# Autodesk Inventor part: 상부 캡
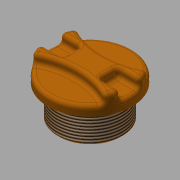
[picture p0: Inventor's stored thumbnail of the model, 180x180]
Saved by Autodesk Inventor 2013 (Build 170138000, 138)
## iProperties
Created: 2016-09
Part Number: 상부 캡
Material: PC/ABS 플라스틱
Document SubType Name: Modeling
Designer: mduedu
Density: 1.493 g/cm^3
Author: mduedu
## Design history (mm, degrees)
sketch "스케치1"
  geometry: C1 r 22.5 at (0, 0); 1 further point
  constraints: 1 centre point, 1 coincident
  dimensions: "d0" = 45 diameter of C1
extrude "돌출1" new body sketch "스케치1" distance "d1" = 10; taper "d2" = 0 deg
sketch "스케치2" dims "d4" = 80
  geometry: C1 r 22.5 at (0, 0) reference; 3 further points
  constraints: 3 vertical alignment, 2 other
  dimensions: "d3" = 7 distance of point (0, 7) point (0, 0)
extrude "돌출2" cut sketch "스케치2" distance "d5" = 5; taper "d6" = 0 deg
sketch "스케치3"
  geometry: L1 (-22.5, 0)-(0, 0); L2 (-21.937, 5)-(-10, 5); L3 (-10, 5)-(-10, -5); L4 (-10, -5)-(-21.937, -5); A1 r 22.5 centre (0, 0) between (-19.118, 11.864) and (-19.118, -11.864) reference; A2 r 22.5 centre (0, 0) between (-21.937, 5) and (-21.937, -5); 1 further point
  constraints: 8 end point, 5 point on circle, 2 horizontal, 1 centre point, 1 coincident, 1 parallel, 1 perpendicular, 1 symmetric about line
  dimensions: "d7" = 10 distance from line of L3 point (0, 0); "d8" = 10 distance of L2.end L3.end
extrude "돌출3" cut sketch "스케치3" distance "d9" = 5; taper "d10" = 0 deg
fillet "모깎기1" dims "d11" = 2
fillet "모깎기2" dims "d12" = 2
fillet "모깎기3" dims "d13" = 2
sketch "스케치4"
  geometry: C1 r 17.5 at (0, 0); 1 further point
  constraints: 1 centre point, 1 coincident
  dimensions: "d14" = 35 diameter of C1
extrude "돌출4" join sketch "스케치4" distance "d15" = 17; taper "d16" = 0 deg
sketch "스케치5"
  geometry: C1 r 12.5 at (0, 0); 1 further point
  constraints: 1 centre point, 1 coincident
  dimensions: "d17" = 25 diameter of C1
extrude "돌출5" cut sketch "스케치5" distance "d18" = 10; taper "d19" = 0 deg
fillet "모깎기4" dims "d20" = 3
feature "스레드1" dims "d21" = 10, "d22" = 0
chamfer "모따기1" distance "d23" = 1; stored, may be unused: second distance "d24" = 2, angle "d25" = 45 deg
node "솔리드1"
mirror "대칭1"
mirror "대칭2"
node "투영된 루프1"
